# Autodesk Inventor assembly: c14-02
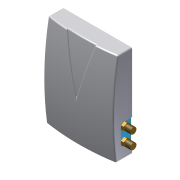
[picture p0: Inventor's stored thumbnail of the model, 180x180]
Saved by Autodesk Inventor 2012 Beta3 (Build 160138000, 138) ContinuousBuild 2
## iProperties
Created: 2011-01
Part Number: c14-02
Document SubType Name: Assembly
Designer: Beta-8540w
Author: Beta-8540w
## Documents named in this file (7)
- C:\Inventor 2012 Essentials\Assemblies\Chapter 14\c14-02.iam
- C:\Inventor 2012 Essentials\Content Center Files\en-US\Parker Hex Nipple 216P\Parker Hex Nipple 216P 216P-4.ipt
- C:\Inventor 2012 Essentials\Parts\Chapter 14\c14-03.ipt
- C:\Inventor 2012 Essentials\Parts\Chapter 14\c14-04.ipt
- C:\Inventor 2012 Essentials\Parts\Chapter 14\c14-05.ipt
- C:\Inventor 2012 Essentials\Parts\Chapter 14\c14-06.ipt
- C:\Inventor 2012 Essentials\Assemblies\Chapter 14\c14-02_Substitute_1.ipt
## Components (7 placed, 6 different names)
1. c14-03:1 — Insert:1, Insert:2, Flush:1, Flush:2, Flush:3, Mate:1, Mate:2, Mate:3
2. Parker Hex Nipple 216P 216P-4:1 — Insert:1
3. Parker Hex Nipple 216P 216P-4:2 — Insert:2
4. c14-04:1 — Flush:3, Mate:1, Mate:2, Mate:3
5. c14-05:1 — Flush:1
6. c14-06:1 — Flush:2
7. c14-02_Substitute_1:1
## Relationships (8: Flush 3, Mate 3, Insert 2)
- Insert:1: c14-03:1 ↔ Parker Hex Nipple 216P 216P-4:1
- Insert:2: c14-03:1 ↔ Parker Hex Nipple 216P 216P-4:2
- Flush:1: c14-03:1 ↔ c14-05:1
- Flush:2: c14-03:1 ↔ c14-06:1
- Flush:3: c14-03:1 ↔ c14-04:1
- Mate:1: c14-03:1 ↔ c14-04:1
- Mate:2: c14-03:1 ↔ c14-04:1
- Mate:3: c14-03:1 ↔ c14-04:1
